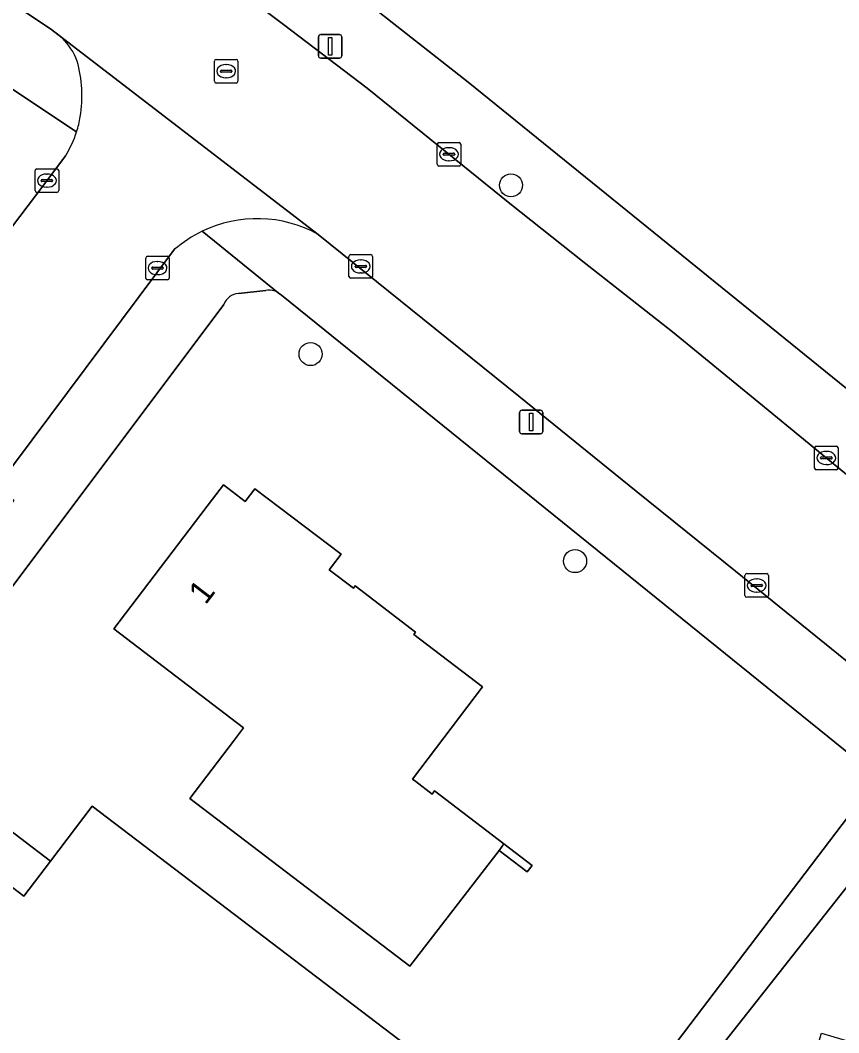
# Model space of a CAD drawing. Extents: x 161139 to 161601, y 381708 to 382245.
# Drawn here: x 161373.8 to 161408.54, y 381886.2 to 381929.18 of the extents above; entities that cross this region are included whole.
import ezdxf

# ---------------------------------------------------------------- set-up
doc = ezdxf.new("R2010")
doc.units = 0
for name, color, linetype in [('IMGEO_Boom', 7, 'Continuous'), ('IMGEO_Erf', 7, 'Continuous'), ('IMGEO_Groenvoorziening', 7, 'Continuous'), ('IMGEO_Kolk', 7, 'Continuous'), ('IMGEO_Lichtmast', 7, 'Continuous'), ('IMGEO_Muur', 7, 'Continuous'), ('IMGEO_Pand', 7, 'Continuous'), ('IMGEO_Pand_nummerreeks', 7, 'Continuous'), ('IMGEO_Rijbaan_lokaal_open', 7, 'Continuous'), ('IMGEO_Rioolput', 7, 'Continuous'), ('IMGEO_Voetpad_op_trap', 7, 'Continuous'), ('IMGEO_Voetpad_open', 7, 'Continuous')]:
    doc.layers.add(name, color=color, linetype=linetype)

msp = doc.modelspace()

# ---------------------------------------------------------------- linework, layer by layer
at = {"layer": 'IMGEO_Boom'}
for centre in [(161394.629, 381922.175), (161386.123, 381915.011), (161397.349, 381906.221)]:
    msp.add_circle(centre, 0.489, dxfattribs=at)
at = {"layer": 'IMGEO_Erf'}
msp.add_lwpolyline([(161301.893, 382073.339), (161290.838, 382055.877), (161287.538, 382048.363), (161285.187, 382041.077), (161283.628, 382034.817), (161278.294, 382002.287), (161281.877, 382000), (161299.823, 381988.353), (161310.674, 381981.109), (161322.611, 381973.432), (161322.712, 381973.551), (161378.924, 381936.994), (161385.641, 381932.206), (161392.817, 381926.552), (161429.313, 381896.994)], dxfattribs=at)
at = {"layer": 'IMGEO_Groenvoorziening'}
for points in [[(161384.224, 381917.711), (161383.062, 381917.586)], [(161410.212, 381897.05), (161384.887, 381917.504), (161384.753, 381917.612)], [(161382.438, 381917.119), (161355.077, 381880.626)], [(161368.776, 381898.292), (161375.084, 381893.489), (161376.851, 381895.819), (161390.838, 381885.171), (161381.677, 381873.144), (161383.219, 381872.094), (161385.019, 381874.335), (161385.244, 381874.499), (161393.345, 381877.126), (161395.275, 381877.818), (161395.877, 381878.224), (161396.293, 381878.738), (161410.212, 381897.05)], [(161425.633, 381884.432), (161423.964, 381885.944), (161411.648, 381895.891), (161396.286, 381876.416), (161398.229, 381877.051), (161404.489, 381875.181), (161404.584, 381875.499), (161407.805, 381886.188), (161423.433, 381881.545), (161420.059, 381870.284), (161418.513, 381865.051), (161414.917, 381852.938), (161413.344, 381847.686), (161410.014, 381836.444), (161394.402, 381841.083), (161397.689, 381852.301)]]:
    msp.add_lwpolyline(points, dxfattribs=at)
msp.add_lwpolyline([(161394.124, 381893.943), (161390.337, 381889.021), (161381.005, 381896.145), (161382.897, 381898.632), (161383.285, 381899.142), (161377.771, 381903.34), (161381.969, 381908.853), (161382.429, 381909.459), (161383.354, 381908.75), (161383.765, 381909.292), (161387.42, 381906.518), (161387.018, 381905.98), (161386.918, 381905.847), (161387.94, 381905.066), (161388.016, 381905.165), (161390.578, 381903.207), (161390.502, 381903.108), (161393.417, 381900.88), (161390.444, 381896.971), (161390.591, 381896.859), (161391.284, 381896.332), (161391.385, 381896.466), (161394.333, 381894.213), (161395.529, 381893.303), (161395.317, 381893.025)], close=True, dxfattribs=at)
for centre, radius, start, end in [((161383.15, 381916.818), 0.773, 96.5423, 157.0799), ((161384.363, 381916.993), 0.731, 57.8011, 100.9988)]:
    msp.add_arc(centre, radius, start, end, dxfattribs=at)
at = {"layer": 'IMGEO_Kolk'}
for p, q in [((161391.498, 381923.066), (161391.498, 381923.918)), ((161391.573, 381923.992), (161392.425, 381923.992)), ((161391.986, 381923.772), (161392.011, 381923.772)), ((161392.499, 381923.918), (161392.499, 381923.066)), ((161391.757, 381923.486), (161391.757, 381923.498)), ((161392.195, 381923.449), (161391.797, 381923.449)), ((161391.8, 381923.535), (161392.198, 381923.535)), ((161392.241, 381923.498), (161392.241, 381923.486)), ((161392.425, 381922.992), (161391.573, 381922.992)), ((161392.009, 381923.212), (161391.984, 381923.212)), ((161374.434, 381921.948), (161374.434, 381922.8)), ((161374.509, 381922.874), (161375.361, 381922.874)), ((161374.922, 381922.654), (161374.947, 381922.654)), ((161375.435, 381922.8), (161375.435, 381921.948)), ((161374.693, 381922.368), (161374.693, 381922.38)), ((161375.131, 381922.331), (161374.733, 381922.331)), ((161374.736, 381922.417), (161375.134, 381922.417)), ((161374.945, 381922.094), (161374.92, 381922.094)), ((161375.177, 381922.38), (161375.177, 381922.368)), ((161375.361, 381921.874), (161374.509, 381921.874)), ((161379.129, 381918.236), (161379.129, 381919.088)), ((161379.204, 381919.162), (161380.056, 381919.162)), ((161380.13, 381919.088), (161380.13, 381918.236)), ((161387.755, 381918.306), (161387.755, 381919.158)), ((161387.83, 381919.232), (161388.682, 381919.232)), ((161388.756, 381919.158), (161388.756, 381918.306)), ((161379.388, 381918.656), (161379.388, 381918.668)), ((161379.826, 381918.619), (161379.428, 381918.619)), ((161379.431, 381918.705), (161379.829, 381918.705)), ((161379.617, 381918.942), (161379.642, 381918.942)), ((161379.872, 381918.668), (161379.872, 381918.656)), ((161388.014, 381918.726), (161388.014, 381918.738)), ((161388.452, 381918.689), (161388.054, 381918.689)), ((161388.057, 381918.775), (161388.455, 381918.775)), ((161388.243, 381919.012), (161388.268, 381919.012)), ((161388.498, 381918.738), (161388.498, 381918.726)), ((161379.64, 381918.382), (161379.615, 381918.382)), ((161388.682, 381918.232), (161387.83, 381918.232)), ((161388.266, 381918.452), (161388.241, 381918.452)), ((161380.056, 381918.162), (161379.204, 381918.162)), ((161407.513, 381910.173), (161407.513, 381911.025)), ((161407.588, 381911.099), (161408.44, 381911.099)), ((161408.001, 381910.879), (161408.026, 381910.879)), ((161408.514, 381911.025), (161408.514, 381910.173)), ((161407.772, 381910.593), (161407.772, 381910.605)), ((161408.21, 381910.556), (161407.812, 381910.556)), ((161407.815, 381910.642), (161408.213, 381910.642)), ((161408.256, 381910.605), (161408.256, 381910.593)), ((161408.44, 381910.099), (161407.588, 381910.099)), ((161408.024, 381910.319), (161407.999, 381910.319)), ((161404.558, 381904.763), (161404.558, 381905.615)), ((161404.633, 381905.689), (161405.485, 381905.689)), ((161405.046, 381905.469), (161405.071, 381905.469)), ((161405.559, 381905.615), (161405.559, 381904.763)), ((161404.817, 381905.183), (161404.817, 381905.195)), ((161405.255, 381905.146), (161404.857, 381905.146)), ((161404.86, 381905.232), (161405.258, 381905.232)), ((161405.069, 381904.909), (161405.044, 381904.909)), ((161405.301, 381905.195), (161405.301, 381905.183)), ((161405.485, 381904.689), (161404.633, 381904.689))]:
    msp.add_line(p, q, dxfattribs=at)
for points in [[(161391.498, 381923.066), (161391.498, 381923.918)], [(161391.573, 381923.992), (161392.425, 381923.992)], [(161392.499, 381923.918), (161392.499, 381923.066)], [(161392.425, 381922.992), (161391.573, 381922.992)], [(161374.434, 381921.948), (161374.434, 381922.8)], [(161374.509, 381922.874), (161375.361, 381922.874)], [(161375.435, 381922.8), (161375.435, 381921.948)], [(161375.361, 381921.874), (161374.509, 381921.874)], [(161379.129, 381918.236), (161379.129, 381919.088)], [(161379.204, 381919.162), (161380.056, 381919.162)], [(161380.13, 381919.088), (161380.13, 381918.236)], [(161387.755, 381918.306), (161387.755, 381919.158)], [(161387.83, 381919.232), (161388.682, 381919.232)], [(161388.756, 381919.158), (161388.756, 381918.306)], [(161388.682, 381918.232), (161387.83, 381918.232)], [(161380.056, 381918.162), (161379.204, 381918.162)], [(161407.513, 381910.173), (161407.513, 381911.025)], [(161407.588, 381911.099), (161408.44, 381911.099)], [(161408.514, 381911.025), (161408.514, 381910.173)], [(161408.44, 381910.099), (161407.588, 381910.099)], [(161404.558, 381904.763), (161404.558, 381905.615)], [(161404.633, 381905.689), (161405.485, 381905.689)], [(161405.559, 381905.615), (161405.559, 381904.763)], [(161405.485, 381904.689), (161404.633, 381904.689)]]:
    msp.add_lwpolyline(points, dxfattribs=at)
for centre, radius, start, end in [((161391.575, 381923.916), 0.0765, 91.552, 178.448), ((161391.575, 381923.916), 0.0765, 91.552, 178.448), ((161392.423, 381923.916), 0.0765, 1.552, 88.448), ((161392.423, 381923.916), 0.0765, 1.552, 88.448), ((161391.797, 381923.495), 0.0403, 85.8775, 175.7526), ((161391.794, 381923.485), 0.0366, 178.938, 274.7102), ((161392.198, 381923.492), 0.043, 264.8664, 352.4533), ((161392.202, 381923.497), 0.0386, 1.7309, 96.639), ((161391.575, 381923.068), 0.0765, 181.552, 268.448), ((161391.575, 381923.068), 0.0765, 181.552, 268.448), ((161392.423, 381923.068), 0.0765, 271.552, 358.448), ((161392.423, 381923.068), 0.0765, 271.552, 358.448), ((161374.511, 381922.798), 0.0765, 91.552, 178.448), ((161374.511, 381922.798), 0.0765, 91.552, 178.448), ((161375.359, 381922.798), 0.0765, 1.552, 88.448), ((161375.359, 381922.798), 0.0765, 1.552, 88.448), ((161374.733, 381922.377), 0.0403, 85.8775, 175.7526), ((161374.73, 381922.367), 0.0366, 178.938, 274.7102), ((161375.134, 381922.374), 0.043, 264.8664, 352.4533), ((161375.138, 381922.379), 0.0386, 1.7309, 96.639), ((161374.511, 381921.95), 0.0765, 181.552, 268.448), ((161374.511, 381921.95), 0.0765, 181.552, 268.448), ((161375.359, 381921.95), 0.0765, 271.552, 358.448), ((161375.359, 381921.95), 0.0765, 271.552, 358.448), ((161379.206, 381919.086), 0.0765, 91.552, 178.448), ((161379.206, 381919.086), 0.0765, 91.552, 178.448), ((161380.054, 381919.086), 0.0765, 1.552, 88.448), ((161380.054, 381919.086), 0.0765, 1.552, 88.448), ((161387.832, 381919.156), 0.0765, 91.552, 178.448), ((161387.832, 381919.156), 0.0765, 91.552, 178.448), ((161388.68, 381919.156), 0.0765, 1.552, 88.448), ((161388.68, 381919.156), 0.0765, 1.552, 88.448), ((161379.428, 381918.665), 0.0403, 85.8775, 175.7526), ((161379.425, 381918.655), 0.0366, 178.938, 274.7102), ((161379.829, 381918.662), 0.043, 264.8664, 352.4533), ((161379.833, 381918.667), 0.0386, 1.7309, 96.639), ((161388.054, 381918.735), 0.0403, 85.8775, 175.7526), ((161388.051, 381918.725), 0.0366, 178.938, 274.7102), ((161388.455, 381918.732), 0.043, 264.8664, 352.4533), ((161388.459, 381918.737), 0.0386, 1.7309, 96.639), ((161379.206, 381918.238), 0.0765, 181.552, 268.448), ((161379.206, 381918.238), 0.0765, 181.552, 268.448), ((161380.054, 381918.238), 0.0765, 271.552, 358.448), ((161380.054, 381918.238), 0.0765, 271.552, 358.448), ((161387.832, 381918.308), 0.0765, 181.552, 268.448), ((161387.832, 381918.308), 0.0765, 181.552, 268.448), ((161388.68, 381918.308), 0.0765, 271.552, 358.448), ((161388.68, 381918.308), 0.0765, 271.552, 358.448), ((161407.59, 381911.023), 0.0765, 91.552, 178.448), ((161407.59, 381911.023), 0.0765, 91.552, 178.448), ((161408.438, 381911.023), 0.0765, 1.552, 88.448), ((161408.438, 381911.023), 0.0765, 1.552, 88.448), ((161407.812, 381910.602), 0.0403, 85.8775, 175.7526), ((161407.809, 381910.592), 0.0366, 178.938, 274.7102), ((161408.213, 381910.599), 0.043, 264.8664, 352.4533), ((161408.217, 381910.604), 0.0386, 1.7309, 96.639), ((161407.59, 381910.175), 0.0765, 181.552, 268.448), ((161407.59, 381910.175), 0.0765, 181.552, 268.448), ((161408.438, 381910.175), 0.0765, 271.552, 358.448), ((161408.438, 381910.175), 0.0765, 271.552, 358.448), ((161404.635, 381905.613), 0.0765, 91.552, 178.448), ((161404.635, 381905.613), 0.0765, 91.552, 178.448), ((161405.483, 381905.613), 0.0765, 1.552, 88.448), ((161405.483, 381905.613), 0.0765, 1.552, 88.448), ((161404.857, 381905.192), 0.0403, 85.8775, 175.7526), ((161404.854, 381905.182), 0.0366, 178.938, 274.7102), ((161405.258, 381905.189), 0.043, 264.8664, 352.4533), ((161405.262, 381905.194), 0.0386, 1.7309, 96.639), ((161404.635, 381904.765), 0.0765, 181.552, 268.448), ((161404.635, 381904.765), 0.0765, 181.552, 268.448), ((161405.483, 381904.765), 0.0765, 271.552, 358.448), ((161405.483, 381904.765), 0.0765, 271.552, 358.448)]:
    msp.add_arc(centre, radius, start, end, dxfattribs=at)
for centre, major_axis, ratio, start_param, end_param in [((161391.985, 381923.492), (-0.387, 0.002), 0.722429, 4.712389, 7.853982), ((161392.01, 381923.492), (-0.39, 0.002), 0.717154, 1.570796, 4.712389), ((161374.921, 381922.374), (-0.387, 0.002), 0.722429, 4.712389, 7.853982), ((161374.946, 381922.374), (-0.39, 0.002), 0.717154, 1.570796, 4.712389), ((161379.616, 381918.662), (-0.387, 0.002), 0.722429, 4.712389, 7.853982), ((161379.641, 381918.662), (-0.39, 0.002), 0.717154, 1.570796, 4.712389), ((161388.242, 381918.732), (-0.387, 0.002), 0.722429, 4.712389, 7.853982), ((161388.267, 381918.732), (-0.39, 0.002), 0.717154, 1.570796, 4.712389), ((161408, 381910.599), (-0.387, 0.002), 0.722429, 4.712389, 7.853982), ((161408.025, 381910.599), (-0.39, 0.002), 0.717154, 1.570796, 4.712389), ((161405.045, 381905.189), (-0.387, 0.002), 0.722429, 4.712389, 7.853982), ((161405.07, 381905.189), (-0.39, 0.002), 0.717154, 1.570796, 4.712389)]:
    msp.add_ellipse(centre, major_axis=major_axis, ratio=ratio, start_param=start_param, end_param=end_param, dxfattribs=at)
at = {"layer": 'IMGEO_Lichtmast'}
for p, q in [((161386.559, 381928.572), (161387.349, 381928.572)), ((161387.349, 381928.572), (161386.559, 381928.572)), ((161386.459, 381927.672), (161386.459, 381928.472)), ((161386.459, 381928.472), (161386.459, 381927.672)), ((161387.449, 381928.472), (161387.449, 381927.672)), ((161387.449, 381927.672), (161387.449, 381928.472)), ((161387.349, 381927.572), (161386.559, 381927.572)), ((161386.559, 381927.572), (161387.349, 381927.572)), ((161395.092, 381912.624), (161395.882, 381912.624)), ((161395.882, 381912.624), (161395.092, 381912.624)), ((161394.992, 381911.724), (161394.992, 381912.524)), ((161394.992, 381912.524), (161394.992, 381911.724)), ((161395.982, 381912.524), (161395.982, 381911.724)), ((161395.982, 381911.724), (161395.982, 381912.524)), ((161395.882, 381911.624), (161395.092, 381911.624)), ((161395.092, 381911.624), (161395.882, 381911.624))]:
    msp.add_line(p, q, dxfattribs=at)
for points in [[(161386.879, 381928.447), (161387.029, 381928.447), (161387.029, 381927.697), (161386.879, 381927.697), (161386.879, 381928.447)], [(161395.412, 381912.499), (161395.562, 381912.499), (161395.562, 381911.749), (161395.412, 381911.749), (161395.412, 381912.499)]]:
    msp.add_lwpolyline(points, dxfattribs=at)
for centre, start, end in [((161386.559, 381928.472), 90, 180), ((161386.559, 381928.472), 90, 180), ((161387.349, 381928.472), 0, 90), ((161387.349, 381928.472), 360, 90), ((161386.559, 381927.672), 180, 270), ((161386.559, 381927.672), 180, 270), ((161387.349, 381927.672), 270, 0), ((161387.349, 381927.672), 270, 0), ((161395.092, 381912.524), 90, 180), ((161395.092, 381912.524), 90, 180), ((161395.882, 381912.524), 0, 90), ((161395.882, 381912.524), 360, 90), ((161395.092, 381911.724), 180, 270), ((161395.092, 381911.724), 180, 270), ((161395.882, 381911.724), 270, 0), ((161395.882, 381911.724), 270, 0)]:
    msp.add_arc(centre, 0.1, start, end, dxfattribs=at)
at = {"layer": 'IMGEO_Muur'}
msp.add_lwpolyline([(161394.333, 381894.213), (161394.124, 381893.943), (161395.317, 381893.025), (161395.529, 381893.303)], close=True, dxfattribs=at)
at = {"layer": 'IMGEO_Pand'}
for points in [[(161390.502, 381903.108), (161390.578, 381903.207), (161388.016, 381905.165), (161387.94, 381905.066), (161386.918, 381905.847), (161387.018, 381905.98), (161387.42, 381906.518), (161383.765, 381909.292), (161383.354, 381908.75), (161382.429, 381909.459), (161381.969, 381908.853), (161377.771, 381903.34), (161383.285, 381899.142), (161382.897, 381898.632), (161381.005, 381896.145), (161390.337, 381889.021), (161394.124, 381893.943), (161394.333, 381894.213), (161391.385, 381896.466), (161391.284, 381896.332), (161390.591, 381896.859), (161390.444, 381896.971), (161393.417, 381900.88)], [(161390.838, 381885.171), (161376.851, 381895.819), (161375.084, 381893.489), (161373.955, 381892.001), (161370.262, 381894.819), (161369.955, 381894.435), (161364, 381886.63), (161365.51, 381885.478), (161362.5, 381881.493), (161362.266, 381881.673), (161355.333, 381872.637), (161355.437, 381872.558), (161368.964, 381862.254), (161371.759, 381860.122), (161374.079, 381863.168), (161378.602, 381869.107), (161378.802, 381869.369), (161381.677, 381873.144)]]:
    msp.add_lwpolyline(points, close=True, dxfattribs=at)
at = {"layer": 'IMGEO_Rijbaan_lokaal_open'}
for points in [[(161372.037, 381930.857), (161375.083, 381928.811), (161386.448, 381920.091), (161391.403, 381916.091), (161394.957, 381913.221), (161399.947, 381909.192), (161404.152, 381905.797), (161425.057, 381888.885), (161426.69, 381887.564), (161430.53, 381892.26), (161428.93, 381893.541), (161416.582, 381903.762), (161409.42, 381909.443), (161405.146, 381912.95), (161401.483, 381915.955), (161397.742, 381918.904), (161394.58, 381921.397), (161388.533, 381926.301), (161384.971, 381929.006), (161381.728, 381931.469)], [(161386.448, 381920.091), (161375.083, 381928.811), (161375.58, 381928.429)], [(161375.72, 381923.419), (161374.759, 381922.138), (161373.481, 381920.434), (161368.51, 381913.776), (161358.116, 381900.025), (161357.581, 381899.312), (161355.178, 381896.112), (161351.589, 381891.33), (161347.78, 381886.211)], [(161352.722, 381882.533), (161364.546, 381898.333), (161367.452, 381902.216), (161368.658, 381903.827), (161372.8, 381909.362), (161380.355, 381919.457)], [(161410.212, 381897.05), (161396.293, 381878.738), (161395.877, 381878.224), (161395.275, 381877.818), (161393.345, 381877.126), (161385.244, 381874.499), (161385.019, 381874.335), (161383.219, 381872.094), (161381.677, 381873.144), (161378.802, 381869.369), (161379.167, 381869.023)], [(161389.585, 381851.709), (161389.721, 381851.996), (161392.214, 381859.719), (161387.882, 381861.165), (161389.294, 381866.012), (161390.047, 381867.09), (161389.223, 381867.644), (161389.02, 381867.798), (161388.983, 381867.825), (161384.784, 381871), (161384.544, 381871.18), (161385.946, 381873.035), (161396.286, 381876.416), (161411.648, 381895.891)]]:
    msp.add_lwpolyline(points, dxfattribs=at)
for centre, radius, start, end in [((161373.726, 381926.514), 2.665, 20.4952, 45.9372), ((161370.758, 381925.969), 5.662, 351.033, 15.1277), ((161371.818, 381925.841), 4.594, 342.3049, 350.5484), ((161371.797, 381925.858), 4.62, 328.1286, 342.1866), ((161383.857, 381915.406), 5.354, 61.0553, 115.876), ((161383.842, 381915.422), 5.333, 115.8141, 130.8365)]:
    msp.add_arc(centre, radius, start, end, dxfattribs=at)
at = {"layer": 'IMGEO_Rioolput'}
for p, q in [((161382.043, 381926.591), (161382.043, 381927.443)), ((161382.118, 381927.517), (161382.97, 381927.517)), ((161382.531, 381927.297), (161382.556, 381927.297)), ((161383.044, 381927.443), (161383.044, 381926.591)), ((161382.302, 381927.011), (161382.302, 381927.023)), ((161382.74, 381926.974), (161382.342, 381926.974)), ((161382.345, 381927.06), (161382.743, 381927.06)), ((161382.786, 381927.023), (161382.786, 381927.011)), ((161382.97, 381926.517), (161382.118, 381926.517)), ((161382.554, 381926.737), (161382.529, 381926.737))]:
    msp.add_line(p, q, dxfattribs=at)
for points in [[(161382.043, 381926.591), (161382.043, 381927.443)], [(161382.118, 381927.517), (161382.97, 381927.517)], [(161383.044, 381927.443), (161383.044, 381926.591)], [(161382.97, 381926.517), (161382.118, 381926.517)]]:
    msp.add_lwpolyline(points, dxfattribs=at)
for centre, radius, start, end in [((161382.12, 381927.441), 0.0765, 91.552, 178.448), ((161382.12, 381927.441), 0.0765, 91.552, 178.448), ((161382.968, 381927.441), 0.0765, 1.552, 88.448), ((161382.968, 381927.441), 0.0765, 1.552, 88.448), ((161382.342, 381927.02), 0.0403, 85.8775, 175.7526), ((161382.339, 381927.01), 0.0366, 178.938, 274.7102), ((161382.743, 381927.017), 0.043, 264.8664, 352.4533), ((161382.747, 381927.022), 0.0386, 1.7309, 96.639), ((161382.12, 381926.593), 0.0765, 181.552, 268.448), ((161382.12, 381926.593), 0.0765, 181.552, 268.448), ((161382.968, 381926.593), 0.0765, 271.552, 358.448), ((161382.968, 381926.593), 0.0765, 271.552, 358.448)]:
    msp.add_arc(centre, radius, start, end, dxfattribs=at)
for centre, major_axis, ratio, start_param, end_param in [((161382.53, 381927.017), (-0.387, 0.002), 0.722429, 4.712389, 7.853982), ((161382.555, 381927.017), (-0.39, 0.002), 0.717154, 1.570796, 4.712389)]:
    msp.add_ellipse(centre, major_axis=major_axis, ratio=ratio, start_param=start_param, end_param=end_param, dxfattribs=at)
at = {"layer": 'IMGEO_Voetpad_op_trap'}
msp.add_lwpolyline([(161368.743, 381898.317), (161367.614, 381896.841), (161370.262, 381894.819), (161373.955, 381892.001), (161375.084, 381893.489), (161368.776, 381898.292)], close=True, dxfattribs=at)
at = {"layer": 'IMGEO_Voetpad_open'}
for points in [[(161327.462, 381959.489), (161318.89, 381965.138), (161315.173, 381967.548), (161315.062, 381967.62), (161311.114, 381970.18), (161307.482, 381972.536), (161299.753, 381977.533), (161278.323, 381991.478), (161276.309, 381989.126), (161370.462, 381928.258), (161376.195, 381924.445)], [(161375.58, 381928.429), (161375.083, 381928.811), (161372.037, 381930.857), (161366.222, 381934.52), (161357.825, 381939.931), (161350.625, 381944.584), (161346.638, 381947.161), (161337.714, 381952.958), (161330.866, 381957.332), (161327.462, 381959.489)], [(161381.728, 381931.469), (161384.971, 381929.006), (161388.533, 381926.301), (161394.58, 381921.397), (161397.742, 381918.904), (161401.483, 381915.955), (161405.146, 381912.95), (161409.42, 381909.443), (161416.582, 381903.762), (161428.93, 381893.541), (161430.53, 381892.26), (161431.607, 381891.362), (161433.377, 381893.414), (161429.313, 381896.994), (161392.817, 381926.552), (161385.641, 381932.206)], [(161376.195, 381924.445), (161370.462, 381928.258)], [(161347.78, 381886.211), (161351.589, 381891.33), (161355.178, 381896.112), (161357.581, 381899.312), (161358.116, 381900.025), (161368.51, 381913.776), (161373.481, 381920.434), (161374.759, 381922.138), (161375.72, 381923.419)], [(161384.753, 381917.612), (161381.52, 381920.223)], [(161381.52, 381920.223), (161384.753, 381917.612), (161384.887, 381917.504), (161410.212, 381897.05), (161411.648, 381895.891), (161423.964, 381885.944), (161425.633, 381884.432), (161427.654, 381886.777), (161426.69, 381887.564), (161425.057, 381888.885), (161404.152, 381905.797)], [(161404.152, 381905.797), (161399.947, 381909.192), (161394.957, 381913.221), (161391.403, 381916.091), (161386.448, 381920.091)], [(161380.355, 381919.457), (161372.8, 381909.362), (161373.53, 381908.815), (161369.388, 381903.281), (161368.658, 381903.827), (161367.452, 381902.216), (161364.546, 381898.333), (161352.722, 381882.533)], [(161383.062, 381917.586), (161384.224, 381917.711)], [(161355.077, 381880.626), (161382.438, 381917.119)]]:
    msp.add_lwpolyline(points, dxfattribs=at)
for centre, radius, start, end in [((161373.726, 381926.514), 2.665, 20.4952, 45.9372), ((161370.758, 381925.969), 5.662, 351.033, 15.1277), ((161371.818, 381925.841), 4.594, 342.3049, 350.5484), ((161371.797, 381925.858), 4.62, 328.1286, 342.1866), ((161383.857, 381915.406), 5.354, 61.0553, 115.876), ((161383.842, 381915.422), 5.333, 115.8141, 130.8365), ((161383.15, 381916.818), 0.773, 96.5423, 157.0799), ((161384.363, 381916.993), 0.731, 57.8011, 100.9988)]:
    msp.add_arc(centre, radius, start, end, dxfattribs=at)

# ---------------------------------------------------------------- texts
at = {"layer": 'IMGEO_Pand_nummerreeks'}
msp.add_text('1', height=1, rotation=52.5116, dxfattribs=at).set_placement((161381.668, 381904.333))

doc.saveas('drawing.dxf')
